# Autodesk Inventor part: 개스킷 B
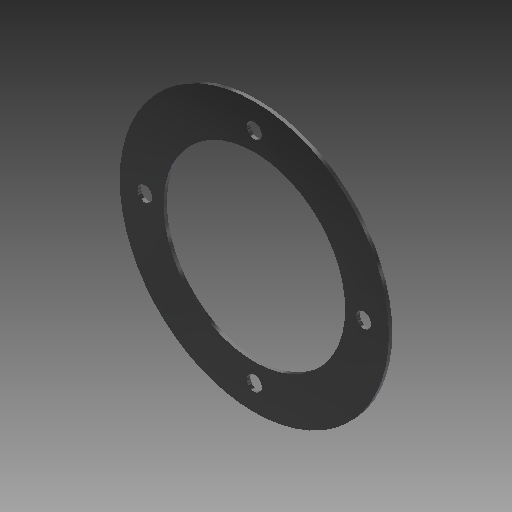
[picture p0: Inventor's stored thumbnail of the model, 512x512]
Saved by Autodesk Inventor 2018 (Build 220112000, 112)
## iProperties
Created: 2019-10
Part Number: 개스킷 B
Material: 고무
Document SubType Name: Modeling
Designer: mduedu
Density: 1 g/cm^3
Appearance: 고무 - 검은색 - 버전 1.1
Author: mduedu
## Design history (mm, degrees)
sketch "스케치1"
  geometry: C1 r 40 at (0, 0); C2 r 27 at (0, 0); 1 further point
  constraints: 2 centre point, 2 coincident
  dimensions: "d0" = 80 diameter of C1; "d1" = 54 diameter of C2
extrude "돌출1" new body sketch "스케치1" distance "d2" = 1; taper "d3" = 0 deg
sketch "스케치2" dims "d4" = 65
  geometry: C1 r 2.25 at (0, 32.5); 2 further points
  constraints: 2 vertical alignment, 1 centre point, 1 coincident, 2 other
  dimensions: "d5" = 4.5 diameter of C1
extrude "돌출2" cut sketch "스케치2" extent not by distance; stored distance "d6" = 1; taper "d7" = 0 deg
node "솔리드1"
pattern_circular "원형 패턴1" dims angle "d9" = 360 deg
